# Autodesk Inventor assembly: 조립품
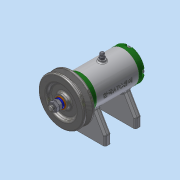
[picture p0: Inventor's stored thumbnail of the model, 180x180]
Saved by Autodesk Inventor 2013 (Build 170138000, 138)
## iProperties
Created: 2018-05
Part Number: 조립품
Document SubType Name: Assembly
Designer: dgall
Author: dgall
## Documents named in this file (16)
- C:\Users\dgall\Desktop\480507V1006\조립품.iam
- C:\Users\dgall\Desktop\480507V1006\본체.ipt
- C:\Users\dgall\Desktop\480507V1006\볼트 M4x12.ipt
- C:\Users\dgall\Desktop\480507V1006\볼트 M6x8.ipt
- C:\Users\dgall\Desktop\480507V1006\스프링와셔 8.ipt
- C:\Users\dgall\Desktop\480507V1006\앞커버.ipt
- C:\Users\dgall\Desktop\480507V1006\오일 실 15 25 7.ipt
- C:\Users\dgall\Desktop\480507V1006\와셔 6x11.5.ipt
- C:\Users\dgall\Desktop\480507V1006\와셔 8x17.ipt
- C:\Users\dgall\Desktop\480507V1006\축.ipt
- C:\Users\dgall\Desktop\480507V1006\키 3x3x12.ipt
- C:\Users\dgall\Desktop\480507V1006\뒤커버.ipt
- C:\Users\dgall\Desktop\480507V1006\V벨트풀리.ipt
- C:\Users\dgall\Desktop\480507V1006\너트 M8.ipt
- C:\Users\dgall\Desktop\480507V1006\니플 M6x0.75.ipt
- C:\Users\dgall\Desktop\480507V1006\베어링 6002.ipt
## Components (1 placed, 1 different names)
1. V벨트풀리:1
